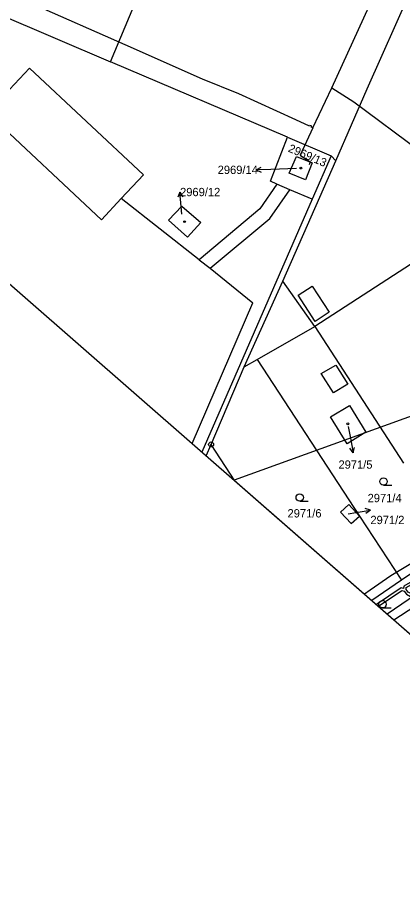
# Model space of a CAD drawing. Extents: x -620475 to -619963, y -1123010 to -1122510.
# Drawn here: x -620299.9 to -620221.2, y -1123010.1 to -1122830.6 of the extents above; entities that cross this region are included whole.
import ezdxf

# ---------------------------------------------------------------- set-up
doc = ezdxf.new("R2010")
doc.units = 0
for name, color, linetype in [('CETIN', 7, 'Continuous'), ('GasNet', 7, 'Continuous'), ('Hranice parcel', 7, 'Continuous'), ('Parcelní čísla', 7, 'Continuous'), ('Pop  PČ popisy', 7, 'Continuous'), ('Rámečky', 7, 'Continuous'), ('Rámečky-tisk', 7, 'Continuous'), ('VAS vodovod', 7, 'Continuous'), ('Vnitřní kresba', 7, 'Continuous'), ('Věcná břemena k části', 7, 'Continuous'), ('Značky bodu BP', 7, 'Continuous'), ('Značky budov', 7, 'Continuous'), ('Značky kultur', 7, 'Continuous')]:
    doc.layers.add(name, color=color, linetype=linetype)

msp = doc.modelspace()

# ---------------------------------------------------------------- linework, layer by layer
at = {"layer": 'CETIN'}
msp.add_lwpolyline([(-620222.97, -1122953.74), (-620218.63, -1122950.99), (-620187.55, -1122931.18), (-620162.84, -1122907.83)], dxfattribs=at)
at = {"layer": 'GasNet'}
for points in [[(-620239.48, -1122853.1), (-620235.63, -1122844.92), (-620221.12, -1122813.09), (-620209.17, -1122785.61)], [(-620301.1, -1122826.47), (-620296.87, -1122827.75), (-620277.93, -1122836.04)], [(-620277.93, -1122836.04), (-620262.14, -1122843.08), (-620254.68, -1122846.1), (-620243.05, -1122851.38), (-620240.27, -1122852.72), (-620240.18, -1122852.54), (-620240, -1122852.62)], [(-620235.63, -1122844.92), (-620231.14, -1122847.8), (-620217.58, -1122857.86), (-620213.36, -1122861.37), (-620199.12, -1122875.88), (-620195.29, -1122879.33), (-620189.1, -1122878.17)], [(-620239.48, -1122853.1), (-620242.07, -1122858.74), (-620240.05, -1122860.1)], [(-620240, -1122852.62), (-620239.82, -1122852.71), (-620239.91, -1122852.89), (-620239.57, -1122853.05), (-620239.48, -1122853.1)], [(-620240.05, -1122860.1), (-620240.29, -1122860.71)]]:
    msp.add_lwpolyline(points, dxfattribs=at)
at = {"layer": 'Hranice parcel'}
for p, q in [((-620318.73, -1122823.4), (-620280.92, -1122839.64)), ((-620244.68, -1122855.06), (-620280.92, -1122839.64)), ((-620244.68, -1122855.06), (-620235.77, -1122858.86)), ((-620234.78, -1122859.86), (-620235.77, -1122858.86)), ((-620250.91, -1122900.53), (-620239.08, -1122893.74)), ((-620239.08, -1122893.74), (-620220.99, -1122921.7)), ((-620253.53, -1122902.03), (-620250.91, -1122900.53)), ((-620260.32, -1122917.88), (-620253.53, -1122902.03)), ((-620261.31, -1122920.2), (-620260.32, -1122917.88)), ((-620255.45, -1122925.33), (-620260.32, -1122917.88)), ((-620210.21, -1122937.96), (-620221.39, -1122945.68)), ((-620224.32, -1122952.56), (-620208, -1122941.31)), ((-620221.39, -1122945.68), (-620227.42, -1122949.84))]:
    msp.add_line(p, q, dxfattribs=at)
for points in [[(-620280.92, -1122839.64), (-620267.15, -1122806.71), (-620246.32, -1122763.41)], [(-620234.78, -1122859.86), (-620228.39, -1122845.14), (-620201.6, -1122784.9)], [(-620152.84, -1122837.4), (-620157.72, -1122840.99), (-620239.08, -1122893.74)], [(-620301.53, -1122845.3), (-620297.45, -1122840.93), (-620274.13, -1122862.72)], [(-620274.13, -1122862.72), (-620278.69, -1122867.6), (-620282.72, -1122871.91), (-620306.02, -1122850.12)], [(-620235.77, -1122858.86), (-620239.62, -1122867.69), (-620244.23, -1122865.77), (-620246.9, -1122864.61), (-620248.18, -1122864.05), (-620244.68, -1122855.06)], [(-620253.53, -1122902.03), (-620245.67, -1122884.47), (-620234.78, -1122859.86)], [(-620239.62, -1122860.31), (-620241.03, -1122863.75), (-620244.32, -1122862.42), (-620242.88, -1122858.98), (-620239.62, -1122860.31)], [(-620262.45, -1122872.51), (-620265.17, -1122875.49), (-620269.05, -1122872.04), (-620266.28, -1122869.15), (-620262.45, -1122872.51)], [(-620250.91, -1122900.53), (-620229.95, -1122932.57), (-620221.39, -1122945.68)], [(-620228.65, -1122915.4), (-620232.52, -1122917.77), (-620235.88, -1122912.25), (-620231.99, -1122909.89), (-620228.65, -1122915.4)], [(-620229.95, -1122932.57), (-620232.13, -1122930.14), (-620233.86, -1122931.77)], [(-620233.86, -1122931.77), (-620231.67, -1122934.08), (-620229.95, -1122932.57)]]:
    msp.add_lwpolyline(points, dxfattribs=at)
at = {"layer": 'Pop  PČ popisy'}
for p, q in [((-620251.09, -1122861.73), (-620250.11, -1122861.19)), ((-620248.09, -1122861.62), (-620251.09, -1122861.73)), ((-620251.09, -1122861.73), (-620250.07, -1122862.19)), ((-620242.88, -1122861.46), (-620248.09, -1122861.62)), ((-620266.68, -1122866.25), (-620267.09, -1122867.29)), ((-620266.42, -1122869.24), (-620266.68, -1122866.25)), ((-620266.68, -1122866.25), (-620266.09, -1122867.2)), ((-620266.29, -1122870.78), (-620266.42, -1122869.24)), ((-620232.3, -1122914.19), (-620231.83, -1122916.62)), ((-620231.83, -1122916.62), (-620231.26, -1122919.57)), ((-620231.26, -1122919.57), (-620231.94, -1122918.68)), ((-620231.26, -1122919.57), (-620230.96, -1122918.49)), ((-620232.28, -1122932.09), (-620230.7, -1122931.83)), ((-620230.7, -1122931.83), (-620227.74, -1122931.36)), ((-620227.74, -1122931.36), (-620228.8, -1122931.02)), ((-620227.74, -1122931.36), (-620228.65, -1122932.01))]:
    msp.add_line(p, q, dxfattribs=at)
at = {"layer": 'Rámečky'}
for points in [[(-620279.07, -1122510.07), (-620474.61, -1122733.62), (-620158.49, -1123010.14)], [(-620126.7, -1122973.8), (-620157.19, -1122889.6), (-620255.57, -1122925.22)], [(-620255.57, -1122925.22), (-620158.49, -1123010.14), (-620126.7, -1122973.8)]]:
    msp.add_lwpolyline(points, dxfattribs=at)
at = {"layer": 'Rámečky-tisk'}
for points in [[(-620279.07, -1122510.07), (-620474.61, -1122733.62), (-620158.49, -1123010.14)], [(-620126.7, -1122973.8), (-620157.19, -1122889.6), (-620255.57, -1122925.22)], [(-620255.57, -1122925.22), (-620158.49, -1123010.14), (-620126.7, -1122973.8)]]:
    msp.add_lwpolyline(points, dxfattribs=at)
at = {"layer": 'VAS vodovod'}
msp.add_lwpolyline([(-620163.36, -1122996), (-620164.27, -1122995.59), (-620165.18, -1122995.18), (-620166.54, -1122992.66), (-620167.89, -1122990.14), (-620169.38, -1122987.78), (-620170.86, -1122985.43), (-620175.49, -1122977.69), (-620180.12, -1122969.95), (-620186.4, -1122959.11), (-620192.67, -1122948.28), (-620196.69, -1122941.97), (-620200.71, -1122935.66), (-620201.19, -1122934.8), (-620201.57, -1122934.15), (-620201.95, -1122933.49), (-620206.59, -1122935.78), (-620211.24, -1122938.06), (-620213.31, -1122938.98), (-620215.39, -1122939.89), (-620219.47, -1122942.33), (-620223.56, -1122944.78), (-620227.81, -1122947.72), (-620228.96, -1122948.51)], dxfattribs=at)
at = {"layer": 'Vnitřní kresba'}
for p, q in [((-620246.9, -1122864.61), (-620250.37, -1122869.68)), ((-620248.3, -1122871.67), (-620244.23, -1122865.77)), ((-620262.79, -1122880.12), (-620278.69, -1122867.6)), ((-620239.62, -1122867.69), (-620262.18, -1122919.44)), ((-620250.37, -1122869.68), (-620262.79, -1122880.12)), ((-620260.48, -1122881.85), (-620248.3, -1122871.67)), ((-620262.79, -1122880.12), (-620260.48, -1122881.85)), ((-620260.48, -1122881.85), (-620251.76, -1122888.93)), ((-620239.08, -1122893.74), (-620245.67, -1122884.47)), ((-620242.49, -1122887.38), (-620239.68, -1122885.51)), ((-620239.68, -1122885.51), (-620236.19, -1122890.86)), ((-620264.19, -1122917.69), (-620251.76, -1122888.93)), ((-620239.05, -1122892.73), (-620242.49, -1122887.38)), ((-620236.19, -1122890.86), (-620239.05, -1122892.73)), ((-620237.8, -1122903.34), (-620234.8, -1122901.69)), ((-620235.3, -1122907.35), (-620237.8, -1122903.34)), ((-620234.8, -1122901.69), (-620232.38, -1122905.55)), ((-620232.38, -1122905.55), (-620235.3, -1122907.35))]:
    msp.add_line(p, q, dxfattribs=at)
at = {"layer": 'Věcná břemena k části'}
msp.add_line((-620226.5, -1122950.65), (-620226.11, -1122951), dxfattribs=at)
msp.add_lwpolyline([(-620226.11, -1122951), (-620221.34, -1122947.77), (-620220.85, -1122947.88), (-620220.38, -1122948.48), (-620219.54, -1122948.96), (-620219.3, -1122948.52), (-620220.04, -1122948.1), (-620220.45, -1122947.58), (-620220.43, -1122947.18), (-620215.58, -1122944.45), (-620213.67, -1122944.01), (-620209.12, -1122941.46), (-620208.72, -1122940.34), (-620210.39, -1122938.08), (-620210.8, -1122938.37), (-620209.28, -1122940.42), (-620209.52, -1122941.12), (-620213.85, -1122943.53), (-620215.76, -1122943.97), (-620220.91, -1122946.88), (-620220.94, -1122947.35), (-620221.44, -1122947.23), (-620226.5, -1122950.65)], dxfattribs=at)
at = {"layer": 'Značky bodu BP'}
for radius in [0.5, 0.0303]:
    msp.add_circle((-620260.32, -1122917.88), radius, dxfattribs=at)
at = {"layer": 'Značky budov'}
for centre in [(-620241.97, -1122861.36), (-620265.74, -1122872.31), (-620232.36, -1122913.67)]:
    msp.add_circle(centre, 0.175, dxfattribs=at)
at = {"layer": 'Značky kultur'}
for p, q in [((-620225.08, -1122926.21), (-620223.33, -1122926.21)), ((-620242.2, -1122929.48), (-620240.45, -1122929.48)), ((-620225.25, -1122951.34), (-620223.5, -1122951.34))]:
    msp.add_line(p, q, dxfattribs=at)
for centre in [(-620225.08, -1122925.46), (-620242.2, -1122928.73), (-620225.25, -1122950.59)]:
    msp.add_circle(centre, 0.75, dxfattribs=at)

# ---------------------------------------------------------------- texts
at = {"layer": 'Parcelní čísla'}
msp.add_text('2969/13', height=1.7, rotation=337, dxfattribs=at).set_placement((-620244.7, -1122857.94))
for s, p in [('2969/14', (-620258.97, -1122862.56)), ('2969/12', (-620266.66, -1122867.1)), ('2971/5', (-620234.27, -1122922.85)), ('2971/4', (-620228.31, -1122929.7)), ('2971/6', (-620244.69, -1122932.82)), ('2971/2', (-620227.74, -1122934.18))]:
    msp.add_text(s, height=1.7, dxfattribs=at).set_placement(p)

doc.saveas('drawing.dxf')
